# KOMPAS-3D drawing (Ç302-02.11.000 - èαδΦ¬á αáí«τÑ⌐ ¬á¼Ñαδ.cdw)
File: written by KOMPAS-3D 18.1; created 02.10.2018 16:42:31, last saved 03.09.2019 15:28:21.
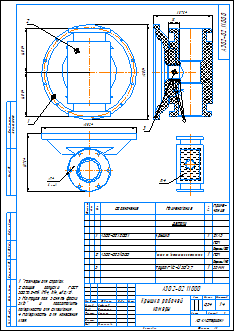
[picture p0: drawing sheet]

Sheet 1: A3, portrait

Document properties: Автор: Милов; Полное имя файла: D:\Мембранные насосы\Мембранный электропривод\А302-00.00.000 - ASTRA-302 (МЭ200)\Чертежи ПВХ\А302-02.11.000 - Крышка рабочей камеры.cdw; Масса: 6.54231

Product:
- Part/product: (unnamed)
  - Component: Крышка  | designation А302-02.12.001  | pos. 1  | Раздел спецификации: Детали; Примечание: 2хА3 / ПВХ / Стержень @2~300
  - Component: Корпус со встроенными стаканами  | designation А302-02.31.000  | pos. 2  | Раздел спецификации: Детали; Примечание: ПВХ / Стержень @2~140
  - Component: Труба PVC-U 50*3,7  | pos. 3  | Раздел спецификации: Детали; Примечание: 35 мм

Title block, sheet 1: Наименование: Крышка рабочей / камеры; designation: А302-02.11.000; Масса: 6,54; scale: 1:4; Количество листов документа: 1; organisation: АО «Астерион»; Форматы листов документа: A3; stored path: \\192.168.87.28\Konstructor_doc\Мембранные насосы\Мембранный электропривод\А302-00.00.000 - ASTRA-302 (МЭ200)\3Д ПВХ\А302-01.11.000 - Крышка рабочей камеры.cdw; Разработал: Лифлянд; Проверил: Борисенко; Т. контр.: Лучихин; Утвердил: Григорьева

Views: Вид 1, Местный разрез 1, Спереди, Проекционный вид 2, Проекционный вид 3, Вид по стрелке 4, Вид:1
Referenced files in D:\Мембранные насосы\Мембранный электропривод\А302-00.00.000 - ASTRA-302 (МЭ200)\3Д ПВХ\: А302-01.31.000 - Корпус со встроенными стаканами.m3d, А302-01.12.001 - Крышка.m3d, А302-01.11.000 - Крышка рабочей камеры.a3d, А302-01.12.000 - Крышка.a3d, А302-01.12.000 - Крышка.cdw, А302-01.31.000 - Корпус.a3d, А302-01.31.000 - Корпус.cdw
Referenced files in D:\1 ПКИ 3D\ПВХ фитинги, трубы\: Труба PVC-U 50 3,7.m3d
Referenced files in Z:\Мембранные насосы\Мембранный электропривод\А302-00.00.000 - ASTRA-302 (МЭ200)\3Д ПВХ\: А302-01.11.000 - Крышка рабочей камеры.a3d
Referenced files in D:\Мембранные насосы\Мембранный электропривод\А302-00.00.000 - ASTRA-302 (МЭ200)\3Д ПВХ\Отработка\: Отвод ПВХ 90гр 50 арт.GIV050.m3d, Отвод ПВХ 45гр 50 арт.HIV050.m3d
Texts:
  Крышка
  Корпус
  Отвод ПВХ 90   50 арт.GIV050
  Отвод ПВХ 90@1~ @2~50 арт.GIV050
  Отвод ПВХ 45   50 арт.HIV050
  Отвод ПВХ 45@1~ @2~50 арт.HIV050
  Труба PVC-U 50*3,7
  Корпус со встроенными стаканами
  ПВХ
  Стержень  300
  2хА3 / ПВХ / Стержень @2~300
  Стержень  140
  ПВХ / Стержень @2~140
  Труба ПВХ PN10 50х2,4
Dimensions and other numbers on the sheet: 3; 35; 187,5; 140,5; 1; 2; 302; 7; 6 отв.; 4; 2хА3; 35 мм; 1:4; 6,54

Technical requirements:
  *Размеры для справок.
  Общие допуски ГОСТ
  30893.2-mK (H14, h14,  t2/2).
  На трубе поз. 3 снять фаски
  3х15  и подготовить
  поверхности для склеивания.
  Поверхность для нанесения
  клея.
